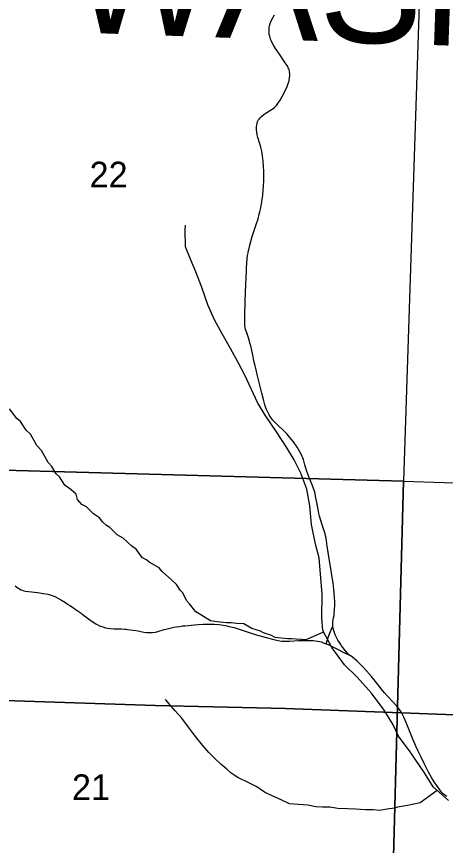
# Model space of a CAD drawing. Extents: x 6.3 to 40.3, y 9 to 31.
# Drawn here: x 9.705 to 10.406, y 27.639 to 28.995 of the extents above; entities that cross this region are included whole.
import ezdxf

# ---------------------------------------------------------------- set-up
doc = ezdxf.new("R2010")
doc.units = 0
for name, color, linetype in [('Default', 7, 'Continuous'), ('GM_X_County_Road', 7, 'Continuous'), ('GM_X_County_Text', 7, 'Continuous'), ('GM_X_Minor_River', 7, 'Continuous'), ('GM_X_Section', 7, 'Continuous'), ('GM_X_Section_Text', 7, 'Continuous'), ('GM_X_Township_Road', 7, 'Continuous')]:
    doc.layers.add(name, color=color, linetype=linetype)

msp = doc.modelspace()

# ---------------------------------------------------------------- linework, layer by layer
at = {"layer": 'Default'}
msp.add_lwpolyline([(13.1323, 29.9457), (8.4446, 29.9457), (8.4446, 27.9161), (8.9627, 27.9002), (9.9314, 27.8681), (10.145, 27.8635), (10.7129, 27.8423), (11.7175, 27.8106), (12.5872, 27.7766), (13.0625, 27.76), (13.0974, 28.6191), (13.1136, 29.1637), (13.1156, 29.231), (13.116, 29.2473), (13.13, 29.8856)], close=True, dxfattribs=at)
msp.add_lwpolyline([(12.5872, 27.7766), (11.7175, 27.8106), (10.7129, 27.8423), (10.145, 27.8635), (9.9314, 27.8681), (8.9627, 27.9002), (8.4446, 27.9161), (8.4446, 23.1457)], dxfattribs=at)
at = {"layer": 'GM_X_County_Road'}
for points in [[(10.2222, 27.9982), (10.222, 28.0006), (10.222, 28.0022), (10.2224, 28.0056), (10.2234, 28.0114), (10.2242, 28.0156), (10.2246, 28.0187), (10.2252, 28.0255), (10.2255, 28.0317), (10.2254, 28.038), (10.225, 28.0455), (10.2238, 28.0578), (10.2225, 28.069), (10.2212, 28.0775), (10.2193, 28.089), (10.2177, 28.0983), (10.2149, 28.1153), (10.2131, 28.1289), (10.2118, 28.1375), (10.2111, 28.1416), (10.2103, 28.1455), (10.2094, 28.1494), (10.208, 28.1536), (10.2049, 28.1634), (10.2026, 28.1705), (10.2006, 28.1776), (10.1994, 28.1824), (10.1986, 28.186), (10.1964, 28.1975), (10.194, 28.2104), (10.1933, 28.2141), (10.1926, 28.2171), (10.1918, 28.2202), (10.1908, 28.2232), (10.1886, 28.229), (10.1842, 28.2396), (10.1812, 28.247), (10.1799, 28.2507), (10.1787, 28.2546), (10.1766, 28.2617), (10.174, 28.2706), (10.1731, 28.2734), (10.1722, 28.2756), (10.1704, 28.2793), (10.1683, 28.2831), (10.1637, 28.2906), (10.1577, 28.2993), (10.1519, 28.3067), (10.1474, 28.3119), (10.1426, 28.3169), (10.1317, 28.3271), (10.1272, 28.3313), (10.1239, 28.3349), (10.1206, 28.3393), (10.118, 28.3434), (10.1157, 28.3477), (10.1133, 28.3533), (10.1112, 28.3597), (10.1089, 28.3687), (10.1062, 28.3789), (10.1029, 28.3922), (10.1002, 28.403), (10.0985, 28.4095), (10.0966, 28.4172), (10.0951, 28.4238), (10.0938, 28.4299), (10.0907, 28.4438), (10.0879, 28.4565), (10.0867, 28.4607), (10.0857, 28.4642), (10.0835, 28.4708), (10.0808, 28.479), (10.0796, 28.4833), (10.0789, 28.4867), (10.0785, 28.4888), (10.0783, 28.4907), (10.0781, 28.494), (10.0782, 28.5014), (10.0784, 28.5093), (10.0785, 28.5146), (10.0787, 28.5194), (10.0789, 28.5267), (10.079, 28.5335), (10.0792, 28.5385), (10.0794, 28.5439), (10.0798, 28.5554), (10.0804, 28.5687), (10.0808, 28.5775), (10.0812, 28.5843), (10.0815, 28.5911), (10.0822, 28.5991), (10.0829, 28.6039), (10.0836, 28.6082), (10.0844, 28.6124), (10.0852, 28.6155), (10.0864, 28.6208), (10.0879, 28.6268), (10.0905, 28.6351), (10.0938, 28.6451), (10.0965, 28.6533), (10.0975, 28.6563), (10.0999, 28.664), (10.1019, 28.6718), (10.1028, 28.6755), (10.1043, 28.6821), (10.1061, 28.6919), (10.1067, 28.6962), (10.1075, 28.7024), (10.1077, 28.7043), (10.1084, 28.7105), (10.1089, 28.7185), (10.1091, 28.7253), (10.1093, 28.7359), (10.1092, 28.7421), (10.109, 28.7496), (10.1084, 28.7583), (10.1074, 28.767), (10.1066, 28.771), (10.1059, 28.7744), (10.1043, 28.781), (10.1027, 28.7864), (10.0997, 28.7971), (10.0986, 28.8016), (10.0978, 28.8062), (10.0975, 28.8089), (10.0973, 28.811), (10.0974, 28.8144), (10.0978, 28.8175), (10.0983, 28.8204), (10.0992, 28.823), (10.1002, 28.8252), (10.1015, 28.8271), (10.1033, 28.8294), (10.1053, 28.8315), (10.1101, 28.8351), (10.1144, 28.8377), (10.1202, 28.8415), (10.1244, 28.8444), (10.1268, 28.8463), (10.1299, 28.8494), (10.1323, 28.8524), (10.1362, 28.8581), (10.1396, 28.8641), (10.1439, 28.8724), (10.1474, 28.8804), (10.1493, 28.8851), (10.1507, 28.8899), (10.1516, 28.8943), (10.152, 28.8981), (10.1519, 28.9013), (10.1516, 28.9036), (10.1512, 28.9055), (10.1506, 28.9076), (10.15, 28.9094), (10.1492, 28.9111), (10.1484, 28.9129), (10.1475, 28.9145), (10.1445, 28.9193), (10.1349, 28.9331), (10.1287, 28.9423), (10.1251, 28.9481), (10.1226, 28.953), (10.1214, 28.9555), (10.1204, 28.958), (10.1196, 28.9603), (10.119, 28.9626), (10.1183, 28.9655), (10.118, 28.9683), (10.1179, 28.9719), (10.1181, 28.9752), (10.1183, 28.9773), (10.1187, 28.9794), (10.1198, 28.9835), (10.1215, 28.988), (10.124, 28.9929), (10.127, 28.9975)], [(10.2483, 27.9509), (10.2408, 27.9602), (10.2383, 27.9633), (10.2364, 27.9659), (10.2351, 27.9681), (10.2331, 27.9713), (10.2303, 27.9753), (10.2292, 27.9774), (10.2281, 27.9796), (10.2262, 27.984), (10.2244, 27.9892), (10.2229, 27.9943), (10.2222, 27.9982)], [(10.4084, 27.7196), (10.4056, 27.7215), (10.4029, 27.7237), (10.4007, 27.7262), (10.3971, 27.7302), (10.3932, 27.7357), (10.3889, 27.7418), (10.3838, 27.7503), (10.3787, 27.7595), (10.3717, 27.7732), (10.366, 27.7849), (10.3617, 27.7938), (10.358, 27.8017), (10.3531, 27.8132), (10.3498, 27.8212), (10.3443, 27.835), (10.3389, 27.8481), (10.3363, 27.8536), (10.3338, 27.8578), (10.3311, 27.8618), (10.3267, 27.867), (10.3201, 27.8743), (10.3121, 27.883), (10.3072, 27.8886), (10.3035, 27.8929), (10.2961, 27.9021), (10.2852, 27.9156), (10.2772, 27.9251), (10.2705, 27.9323), (10.2621, 27.9406), (10.2537, 27.9476), (10.2483, 27.9509)]]:
    msp.add_lwpolyline(points, dxfattribs=at)
at = {"layer": 'GM_X_Minor_River'}
for points in [[(10.4111, 27.7128), (10.3861, 27.7354), (10.3721, 27.7581), (10.3487, 27.7924), (10.3297, 27.8181), (10.3203, 27.8377), (10.3063, 27.8604), (10.2854, 27.8883), (10.262, 27.9144), (10.2415, 27.9348), (10.2203, 27.9631), (10.2056, 27.9907), (10.2041, 28.0118), (10.2045, 28.0503), (10.1999, 28.1096), (10.1939, 28.1323), (10.1871, 28.164), (10.1848, 28.195), (10.1795, 28.2218), (10.1697, 28.2482), (10.1587, 28.2701), (10.1466, 28.2909), (10.1299, 28.3158), (10.1118, 28.343), (10.0989, 28.3638), (10.0789, 28.4072), (10.0675, 28.4291), (10.0546, 28.4521), (10.041, 28.4759), (10.0285, 28.499), (10.0176, 28.5235), (10.0073, 28.5534), (9.9979, 28.5772), (9.9896, 28.5979), (9.9812, 28.6183), (9.9809, 28.6455), (9.9812, 28.6534)], [(10.2069, 27.9882), (10.1779, 27.9757), (10.1548, 27.9773), (10.1479, 27.9773), (10.1278, 27.9797), (10.122, 27.9827), (10.1087, 27.9871), (10.1037, 27.9897), (10.09, 27.9941), (10.0767, 28.0016), (10.0645, 28.0026), (10.0561, 28.0032), (10.0482, 28.0035), (10.0329, 28.0053), (10.0223, 28.0067), (10.0063, 28.0164), (9.9982, 28.0216), (9.9878, 28.0344), (9.9828, 28.0397), (9.977, 28.0525), (9.9728, 28.0571), (9.9666, 28.0661), (9.9589, 28.0732), (9.9429, 28.0875), (9.9382, 28.0932), (9.9218, 28.1029), (9.9176, 28.1062), (9.9107, 28.1096), (9.9073, 28.1145), (9.9007, 28.1239), (9.8934, 28.1288), (9.8792, 28.1419), (9.8697, 28.1475), (9.8574, 28.1592), (9.8521, 28.1625), (9.8459, 28.1682), (9.8405, 28.1749), (9.8306, 28.1817), (9.8195, 28.1933), (9.8115, 28.1967), (9.8045, 28.205), (9.8026, 28.2137), (9.7945, 28.2208), (9.7838, 28.2287), (9.7753, 28.2423), (9.7699, 28.2468), (9.7626, 28.2592), (9.7568, 28.2656), (9.746, 28.2853), (9.7383, 28.2932), (9.7279, 28.312), (9.7206, 28.3184), (9.7113, 28.3324), (9.7056, 28.3377), (9.6933, 28.3531)], [(10.3927, 27.7295), (10.3649, 27.7091), (10.3445, 27.7047), (10.3282, 27.7019), (10.3229, 27.7003), (10.3111, 27.6986), (10.2986, 27.6966), (10.2879, 27.6976), (10.2754, 27.6979), (10.2595, 27.6988), (10.2462, 27.6991), (10.2306, 27.7001), (10.2173, 27.7018), (10.2055, 27.7021), (10.1945, 27.7027), (10.1815, 27.7052), (10.1663, 27.7062), (10.1515, 27.7076), (10.1378, 27.7139), (10.124, 27.7198), (10.1107, 27.7265), (10.0977, 27.7355), (10.0851, 27.7418), (10.0668, 27.7507), (10.0606, 27.7541), (10.0561, 27.7574), (10.0488, 27.7642), (10.0392, 27.7725), (10.0296, 27.7811), (10.0192, 27.7912), (10.0089, 27.8033), (9.9977, 27.8176), (9.9861, 27.833), (9.975, 27.8474), (9.9642, 27.8594), (9.9538, 27.8718), (9.9496, 27.8771), (9.9482, 27.8777)]]:
    msp.add_lwpolyline(points, dxfattribs=at)
at = {"layer": 'GM_X_Section'}
for points in [[(9.3732, 29.268), (10.3703, 29.2306), (10.3378, 28.2352), (9.3471, 28.2622)], [(9.3471, 28.2622), (10.3378, 28.2352), (10.3113, 27.232), (9.3175, 27.262)], [(10.3378, 28.2352), (11.3334, 28.2025), (11.3031, 27.2038), (10.3113, 27.232)]]:
    msp.add_lwpolyline(points, close=True, dxfattribs=at)
at = {"layer": 'GM_X_Township_Road'}
for points in [[(9.7029, 28.0637), (9.7052, 28.0617), (9.7075, 28.0601), (9.7097, 28.0588), (9.7121, 28.0575), (9.7142, 28.0566), (9.7168, 28.0559), (9.7197, 28.0553), (9.7393, 28.0528), (9.7492, 28.0516), (9.7559, 28.0502), (9.7618, 28.0486), (9.7677, 28.0464), (9.7738, 28.0434), (9.7786, 28.0406), (9.7849, 28.0366), (9.7885, 28.0342), (9.7921, 28.0318), (9.7963, 28.0291), (9.8024, 28.0249), (9.8075, 28.0213), (9.8105, 28.0192), (9.8145, 28.0162), (9.8185, 28.0133), (9.8229, 28.01), (9.8265, 28.0075), (9.8305, 28.0046), (9.8347, 28.002), (9.8368, 28.0007), (9.8406, 27.9987), (9.8458, 27.9967), (9.8505, 27.9952), (9.8542, 27.9945), (9.8585, 27.9939), (9.8647, 27.9936), (9.8709, 27.9936), (9.8765, 27.9935), (9.8821, 27.9932), (9.8845, 27.9929), (9.8864, 27.9928), (9.8913, 27.9922), (9.895, 27.9917), (9.8998, 27.9909), (9.9041, 27.9901), (9.9083, 27.9892), (9.9132, 27.9883), (9.9174, 27.9877), (9.9224, 27.9874), (9.9273, 27.9876), (9.9322, 27.9883), (9.9358, 27.9891), (9.9394, 27.9901), (9.943, 27.9913), (9.9465, 27.9924), (9.9489, 27.9931), (9.9537, 27.9943), (9.9579, 27.9952), (9.9622, 27.9961), (9.9664, 27.9969), (9.9719, 27.9977), (9.9762, 27.9983), (9.9805, 27.9987), (9.986, 27.9993), (9.9904, 27.9997), (9.9959, 28.0002), (10.0021, 28.0007), (10.0101, 28.0011), (10.0172, 28.0013), (10.0233, 28.0014), (10.0285, 28.0012), (10.0359, 28.0007), (10.0402, 28.0001), (10.0427, 27.9997), (10.0469, 27.999), (10.0529, 27.9977), (10.0607, 27.9956), (10.0753, 27.991), (10.0952, 27.9846), (10.1134, 27.9793), (10.1258, 27.9761), (10.133, 27.9745), (10.139, 27.9737), (10.1446, 27.9733), (10.1513, 27.9735), (10.1661, 27.9744), (10.1754, 27.9747), (10.1828, 27.9746), (10.19, 27.9744), (10.1937, 27.9741), (10.1974, 27.9735), (10.2004, 27.9729), (10.2033, 27.9721), (10.2065, 27.9709), (10.2115, 27.969)], [(10.2115, 27.969), (10.213, 27.9743), (10.2146, 27.9795), (10.2166, 27.9853), (10.2199, 27.9929), (10.2222, 27.9982)], [(10.2115, 27.969), (10.2145, 27.9678), (10.221, 27.9648), (10.2322, 27.9592), (10.237, 27.9567), (10.2414, 27.9544), (10.2483, 27.9509)]]:
    msp.add_lwpolyline(points, dxfattribs=at)

# ---------------------------------------------------------------- texts
at = {"layer": 'GM_X_County_Text'}
msp.add_text('WASHINGTON COUNTY', height=0.189394, rotation=357.9773, dxfattribs=at).set_placement((9.7904, 28.9692))
at = {"layer": 'GM_X_Section_Text'}
for s, p in [('22', (9.8244, 28.7155)), ('21', (9.7956, 27.7138))]:
    msp.add_text(s, height=0.04186, rotation=0, dxfattribs=at).set_placement(p)

doc.saveas('drawing.dxf')
